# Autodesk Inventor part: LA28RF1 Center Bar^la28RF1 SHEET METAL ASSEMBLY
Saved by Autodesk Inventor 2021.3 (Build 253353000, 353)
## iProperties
Created: 2023-01
Part Number: LA28RF1 Center Bar^la28RF1 SHEET METAL ASSEMBLY
Material: Generic
Document SubType Name: Modeling
Designer: AdminForWorker
Density: 1 g/cm^3
Appearance: Default
Title: LA28RF1 Center Bar^la28RF1 SHEET METAL ASSEMBLY
Author: AdminForWorker
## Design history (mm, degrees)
feature "Cut-Extrude3"
body "Solid1"
